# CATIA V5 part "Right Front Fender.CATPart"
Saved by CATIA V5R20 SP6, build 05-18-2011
Part number: Right Front Fender
Bounding box of the stored display mesh (mm): x -425.059 to 248.261, y -80 to 100, z 65 to 430
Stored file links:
  E:\#03 University\#02 영남 이공대\#01 2021\#02 여름 방학\#01 Documents\K-Move Page02 ASD01\Right Front Fender.CATPart

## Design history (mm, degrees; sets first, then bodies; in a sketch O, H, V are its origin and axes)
Set1 "Reference Data"
  Point1 "Center Point": (0, 0, 0)
  Plane1: type Offset, RefPlane zx-plane, Offset -80
  Plane2: type Offset, RefPlane Plane1, Offset 180
Body1 (main body)
Body2
  Sketch1 on zx-plane, origin (0, 0, 0), H (-1, 0, 0), V (0, 0, 1)
    arc A1 centre (0, 0) radius 430 from (425.0588, 65) to (0, 430) ccw
    line L1 (-219.3931, 380) -> (-248.2606, 430)
    line L2 (-248.2606, 430) -> (0, 430)
    point P2 (0, 430)
    point P4 (425.0588, 65)
    line L3 (-219.3931, 380) -> (0, 380)
    point P5 (-248.2606, 380)
    point P6 (0, 380)
    construction line L4 (-248.2606, 430) -> (-248.2606, 380)
    construction line L5 (0, 430) -> (0, 380)
    arc A2 centre (0, 0) radius 380 from (374.3995, 65) to (0, 380) ccw
    point P7 (0, 380)
    line L6 (425.0588, 65) -> (374.3995, 65)
    radius A1 = 430
    angle H L1 = 60
    distance H P4 = 65
    distance L2 L3 = 50
    coincidence: P2 A1, P2 V, P2 L2, P6 P7, O L1, P5 L3
    horizontal: L2 H, L6 H
    tangency: L2 A1, A2 L3
    perpendicularity: L4 L2, L4 L3, L5 L2, L5 L3
    concentricity: A2 A1
  Pad1: profile Sketch1, direction (0, 1, 0), up to Plane2, opposite side up to Plane1
  Fillet1: radius 50, on edge [face of Pad1 from Sketch1.L3 | face of Pad1 from Sketch1.L1]
  Fillet2: radius 30, on edge [face of Pad1 from Sketch1.L2 | start face of Pad1]
  Shell1: ExtOffset 0, Face (face of Pad1 from Sketch1.A2; face of Pad1 from Sketch1.L3; face of Fillet1; face of Pad1 from Sketch1.L1; face of Pad1 from Sketch1.L6; end face of Pad1), IntOffset 5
